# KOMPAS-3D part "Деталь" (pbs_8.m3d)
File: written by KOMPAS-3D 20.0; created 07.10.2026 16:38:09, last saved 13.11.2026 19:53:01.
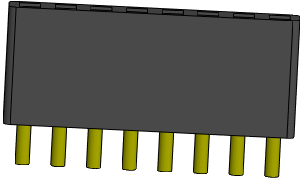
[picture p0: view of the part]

Document properties: Полное имя файла: D:\myProjects\Progect_esp32\box_compas\разъемы\pbs_8.m3d

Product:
- Part/product: Деталь
    Масса: 0.00246148

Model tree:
1. Эскиз:1
2. Элемент выдавливания:1
     Расстояние 1 = 8.5
3. Эскиз:2  (with: Элемент выдавливания:1)
4. Элемент выдавливания:2
     Расстояние 1 = 3
5. Массив по сетке:2  (with: Элемент выдавливания:2, Эскиз:2)  (8 pattern instances)
     Шаг 1 = 2.54; Угол раствора = 90
6. Эскиз:3  (with: Элемент выдавливания:1)
7. Элемент выдавливания:3
     Расстояние 2 = 8
8. Массив по сетке:3  (with: Элемент выдавливания:3, Эскиз:3)  (8 pattern instances)
     Шаг 1 = 2.54; Угол раствора = 90; Геометрический массив = 128
9. Скругление:1  (with: Элемент выдавливания:1)
     Радиус = 0.5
